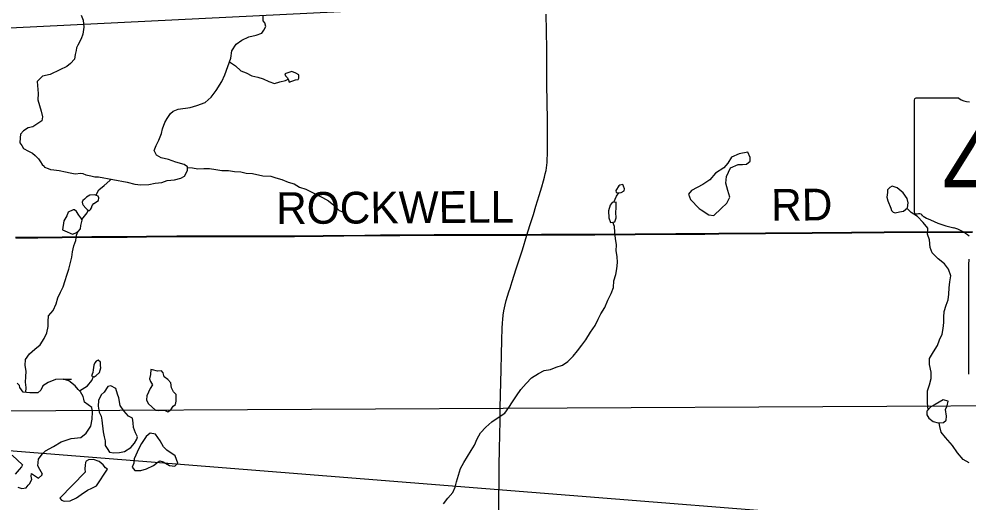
# Model space of a CAD drawing. Extents: x 0 to 34, y 0 to 22.
# Drawn here: x 6.128 to 7.83, y 16.749 to 17.616 of the extents above; entities that cross this region are included whole.
import ezdxf

# ---------------------------------------------------------------- set-up
doc = ezdxf.new("R2010")
doc.units = 0
for name, color, linetype in [('GM_X_Corporation', 7, 'Continuous'), ('GM_X_County_Road', 7, 'Continuous'), ('GM_X_County_Road_Text', 7, 'Continuous'), ('GM_X_Minor_Lake', 7, 'Continuous'), ('GM_X_Minor_River', 7, 'Continuous'), ('GM_X_State_Location', 7, 'Continuous'), ('GM_X_State_Route', 7, 'Continuous'), ('GM_X_State_Shield', 7, 'Continuous'), ('SH_Text', 7, 'Continuous')]:
    doc.layers.add(name, color=color, linetype=linetype)

msp = doc.modelspace()

# ---------------------------------------------------------------- linework, layer by layer
at = {"layer": 'GM_X_Corporation'}
for points in [[(7.8362, 17.2347), (7.6782, 17.2342), (7.6198, 17.2337), (7.549, 17.2329), (7.3818, 17.2314), (7.3564, 17.2312), (7.3048, 17.2311), (7.1593, 17.23), (7.1382, 17.2298), (7.1122, 17.2299), (7.0898, 17.2297), (7.0645, 17.2297), (7.0379, 17.2295), (7.0015, 17.2293), (6.9624, 17.2292), (6.9475, 17.2293), (6.9047, 17.2295), (6.8718, 17.2293), (6.8104, 17.229), (6.7756, 17.2286), (6.7476, 17.2284), (6.6731, 17.2276), (6.6215, 17.227), (6.5929, 17.2268), (6.5569, 17.2268), (6.5314, 17.2268), (6.4817, 17.2268), (6.4688, 17.2268), (6.4502, 17.2269), (6.4107, 17.2268), (6.3562, 17.2263), (6.3215, 17.2259), (6.3059, 17.2258), (6.2767, 17.2256), (6.2587, 17.2255), (6.2053, 17.2252), (6.1792, 17.2248), (6.1618, 17.2246), (6.122, 17.2243)], [(6.122, 17.2243), (6.1618, 17.2246), (6.1792, 17.2248), (6.2053, 17.2252), (6.2587, 17.2255), (6.2767, 17.2256), (6.3059, 17.2258), (6.3215, 17.2259), (6.3562, 17.2263), (6.4107, 17.2268), (6.4502, 17.2269), (6.4688, 17.2268), (6.4817, 17.2268), (6.5314, 17.2268), (6.5569, 17.2268), (6.5929, 17.2268), (6.6215, 17.227), (6.6731, 17.2276), (6.7476, 17.2284), (6.7756, 17.2286), (6.8104, 17.229), (6.8718, 17.2293), (6.9047, 17.2295), (6.9475, 17.2293), (6.9624, 17.2292), (7.0015, 17.2293), (7.0379, 17.2295), (7.0645, 17.2297), (7.0898, 17.2297), (7.1122, 17.2299), (7.1382, 17.2298), (7.1593, 17.23), (7.3048, 17.2311), (7.3564, 17.2312), (7.3818, 17.2314), (7.549, 17.2329), (7.6198, 17.2337), (7.6782, 17.2342), (7.8362, 17.2347)]]:
    msp.add_lwpolyline(points, dxfattribs=at)
at = {"layer": 'GM_X_County_Road'}
for points in [[(7.0381, 17.229), (7.0436, 17.2462), (7.0497, 17.2658), (7.0542, 17.2804), (7.0603, 17.2998), (7.0647, 17.315), (7.068, 17.3262), (7.0695, 17.3323), (7.071, 17.3384), (7.0723, 17.3447), (7.073, 17.3493), (7.0736, 17.3539), (7.0741, 17.3585), (7.0743, 17.3624), (7.0748, 17.3757), (7.0749, 17.3828), (7.0749, 17.3916), (7.0749, 17.407), (7.0748, 17.4352), (7.074, 17.4985), (7.0738, 17.5368), (7.0736, 17.5608), (7.0731, 17.5947), (7.0727, 17.6245)], [(6.1222, 17.2238), (6.162, 17.2241), (6.1794, 17.2243), (6.2055, 17.2246), (6.2589, 17.225), (6.2769, 17.2251), (6.3061, 17.2253), (6.3217, 17.2254), (6.3564, 17.2257), (6.4109, 17.2262), (6.4504, 17.2263), (6.469, 17.2263), (6.4819, 17.2263), (6.5316, 17.2263), (6.5571, 17.2262), (6.5931, 17.2263), (6.6217, 17.2264), (6.6733, 17.2271), (6.7478, 17.2279), (6.7758, 17.2281), (6.8106, 17.2284), (6.872, 17.2287), (6.9049, 17.2289), (6.9477, 17.2288), (6.9626, 17.2287), (7.0017, 17.2288), (7.0381, 17.229)], [(6.9878, 16.7338), (6.988, 16.7499), (6.988, 16.7679), (6.9881, 16.7791), (6.9882, 16.7871), (6.9885, 16.8157), (6.9891, 16.8462), (6.99, 16.8965), (6.9904, 16.9196), (6.9919, 16.9882), (6.9924, 17.0142), (6.9932, 17.0415), (6.9939, 17.0615), (6.9945, 17.0719), (6.9949, 17.0777), (6.9957, 17.0854), (6.9967, 17.0931), (6.9977, 17.0987), (6.999, 17.1039), (7.0012, 17.1116), (7.0057, 17.1271), (7.0078, 17.1336), (7.0117, 17.146), (7.019, 17.1684), (7.0301, 17.2027), (7.0381, 17.229)], [(7.0381, 17.229), (7.0647, 17.2291), (7.09, 17.2291), (7.1124, 17.2293), (7.1384, 17.2293), (7.1595, 17.2294), (7.305, 17.2305), (7.3566, 17.2307), (7.382, 17.2308), (7.5492, 17.2324), (7.62, 17.2331), (7.6784, 17.2336), (7.8364, 17.2342)]]:
    msp.add_lwpolyline(points, dxfattribs=at)
at = {"layer": 'GM_X_Minor_Lake'}
for p, q in [((6.6122, 17.5028), (6.6235, 17.5067)), ((6.2706, 17.333), (6.3218, 17.3235)), ((7.2029, 17.317), (7.1977, 17.3086)), ((6.243, 17.2827), (6.2477, 17.2768)), ((7.331, 17.2925), (7.347, 17.2767)), ((7.347, 17.2767), (7.3318, 17.2922)), ((7.6849, 17.29), (7.6899, 17.2768)), ((7.184, 17.2721), (7.1847, 17.2596)), ((6.2104, 17.2362), (6.2241, 17.2306)), ((6.2619, 16.9958), (6.2608, 16.9874)), ((6.3633, 16.9541), (6.3569, 16.9408)), ((7.7697, 16.9257), (7.7621, 16.9211)), ((6.2763, 16.8977), (6.2787, 16.8765)), ((6.1753, 16.8427), (6.1896, 16.8504)), ((6.3425, 16.8466), (6.3344, 16.8284)), ((6.267, 16.7797), (6.2868, 16.8098))]:
    msp.add_line(p, q, dxfattribs=at)
for points in [[(6.2392, 17.6225), (6.2431, 17.6138), (6.2439, 17.6013), (6.2425, 17.5884), (6.2395, 17.58), (6.2336, 17.569), (6.2313, 17.564), (6.2302, 17.5595), (6.2288, 17.5523), (6.2277, 17.5439), (6.2202, 17.5363), (6.2138, 17.5309), (6.2014, 17.5244), (6.184, 17.5166), (6.17, 17.5135), (6.1606, 17.5036), (6.1623, 17.4823), (6.1617, 17.471), (6.1679, 17.4505), (6.1702, 17.4403), (6.1691, 17.4335), (6.153, 17.4227), (6.1446, 17.4208), (6.136, 17.4154), (6.1307, 17.4093), (6.13, 17.4032), (6.1293, 17.3941), (6.1332, 17.3892), (6.1362, 17.3839), (6.145, 17.3791), (6.1522, 17.3757), (6.1568, 17.3716), (6.1629, 17.3655), (6.1667, 17.3599), (6.1698, 17.355), (6.1732, 17.352), (6.174, 17.3505), (6.18, 17.3478), (6.1842, 17.3464), (6.1906, 17.3457), (6.2001, 17.3442), (6.2115, 17.342), (6.2195, 17.3402), (6.2289, 17.3387), (6.2388, 17.3396), (6.2425, 17.3392), (6.2475, 17.337), (6.257, 17.3352), (6.2638, 17.3333), (6.2706, 17.333)], [(6.3218, 17.3235), (6.3354, 17.3202), (6.3464, 17.3188), (6.3604, 17.3193), (6.3717, 17.322), (6.3842, 17.3229), (6.3937, 17.3267), (6.4069, 17.3276), (6.4182, 17.3307), (6.4246, 17.3345), (6.4298, 17.3444), (6.4302, 17.3513), (6.4237, 17.3554), (6.4093, 17.3591), (6.3956, 17.3643), (6.3827, 17.3672), (6.3744, 17.3717), (6.3705, 17.38), (6.3739, 17.3895), (6.3787, 17.399), (6.3832, 17.4108), (6.385, 17.4192), (6.3894, 17.4306), (6.3935, 17.4378), (6.3992, 17.4466), (6.404, 17.4508), (6.4135, 17.4543), (6.435, 17.4571), (6.4467, 17.461), (6.4614, 17.4664), (6.4724, 17.4756), (6.4813, 17.4878), (6.4914, 17.5038), (6.4966, 17.5156), (6.5022, 17.5305), (6.5074, 17.5453), (6.5092, 17.5589), (6.5174, 17.5708), (6.5272, 17.5777), (6.5396, 17.5835), (6.5529, 17.587), (6.5631, 17.5905), (6.5668, 17.5958), (6.5701, 17.6023), (6.5682, 17.6087), (6.5655, 17.6125), (6.5658, 17.6212)], [(6.6235, 17.5067), (6.628, 17.5075), (6.6295, 17.5098), (6.6295, 17.5155), (6.6242, 17.5185), (6.6166, 17.5215), (6.6041, 17.5176), (6.6053, 17.5142), (6.6087, 17.5108), (6.611, 17.5066), (6.6122, 17.5028)], [(7.4337, 17.3771), (7.4182, 17.3744), (7.4046, 17.3686), (7.3983, 17.3575), (7.3911, 17.3491), (7.3761, 17.3399), (7.3656, 17.3277), (7.3535, 17.3196), (7.3328, 17.3089), (7.3275, 17.302), (7.331, 17.2925)], [(7.347, 17.2767), (7.3505, 17.2741), (7.3638, 17.2651), (7.3729, 17.2637), (7.3864, 17.2763), (7.3962, 17.2862), (7.4014, 17.2965), (7.3979, 17.3086), (7.3948, 17.3218), (7.3958, 17.334), (7.3991, 17.3416), (7.4029, 17.3492), (7.4165, 17.355), (7.4244, 17.3551), (7.4316, 17.3559), (7.438, 17.3609), (7.4379, 17.3677), (7.4337, 17.3771), (7.4182, 17.3744), (7.4046, 17.3686), (7.3983, 17.3575), (7.3911, 17.3491), (7.3761, 17.3399), (7.3656, 17.3277), (7.3535, 17.3196), (7.3328, 17.3089), (7.3275, 17.302), (7.331, 17.2925)], [(7.347, 17.2767), (7.3505, 17.2741), (7.3638, 17.2651), (7.3729, 17.2637), (7.3864, 17.2763), (7.3962, 17.2862), (7.4014, 17.2965), (7.3979, 17.3086), (7.3948, 17.3218), (7.3958, 17.334), (7.3991, 17.3416), (7.4029, 17.3492), (7.4165, 17.355), (7.4244, 17.3551), (7.4316, 17.3559), (7.438, 17.3609), (7.4379, 17.3677), (7.4337, 17.3771)], [(7.1977, 17.3086), (7.1981, 17.3052), (7.2034, 17.3045), (7.2072, 17.3052), (7.2121, 17.3083), (7.2128, 17.3117), (7.2112, 17.3163), (7.2101, 17.3193), (7.2044, 17.3185), (7.2029, 17.317)], [(7.6899, 17.2768), (7.6915, 17.273), (7.6946, 17.27), (7.698, 17.2689), (7.7059, 17.2705), (7.7128, 17.2717), (7.7199, 17.2779), (7.7213, 17.2866), (7.7197, 17.2942), (7.7124, 17.3043), (7.7017, 17.3137), (7.6926, 17.3163), (7.6884, 17.3139), (7.6843, 17.3097), (7.684, 17.3048), (7.6829, 17.2968), (7.6849, 17.29)], [(6.2477, 17.2768), (6.2499, 17.2748), (6.2537, 17.2722), (6.2563, 17.2749), (6.2578, 17.2779), (6.2593, 17.2821), (6.2619, 17.2855), (6.2702, 17.2909), (6.2713, 17.2954), (6.2697, 17.2985), (6.2637, 17.3007), (6.255, 17.3006), (6.2489, 17.2968), (6.2452, 17.293), (6.2422, 17.2907), (6.2414, 17.2876), (6.2418, 17.2846), (6.243, 17.2827)], [(7.1847, 17.2596), (7.1879, 17.2512), (7.1958, 17.2528), (7.1981, 17.26), (7.1976, 17.2691), (7.1979, 17.2779), (7.1978, 17.2877), (7.191, 17.2873), (7.1873, 17.2823), (7.184, 17.2721)], [(6.2241, 17.2306), (6.2286, 17.2322), (6.2343, 17.2352), (6.238, 17.2402), (6.2387, 17.2463), (6.2398, 17.2508), (6.2409, 17.2554), (6.2386, 17.2596), (6.2352, 17.2648), (6.2313, 17.2713), (6.2272, 17.2739), (6.2249, 17.2739), (6.2162, 17.2696), (6.2136, 17.2632), (6.2084, 17.2544), (6.2059, 17.2381), (6.2104, 17.2362)], [(6.2608, 16.9874), (6.2605, 16.9829), (6.2582, 16.9768), (6.2624, 16.9749), (6.2662, 16.9772), (6.2722, 16.9826), (6.2748, 16.9913), (6.274, 16.9955), (6.274, 17.0012), (6.2698, 17.0049), (6.2664, 17.003), (6.2641, 17.0004), (6.2619, 16.9958)], [(6.3569, 16.9408), (6.3566, 16.9339), (6.3597, 16.9271), (6.3669, 16.9208), (6.3723, 16.9155), (6.3787, 16.9148), (6.3889, 16.9156), (6.3946, 16.9126), (6.3999, 16.9161), (6.404, 16.9226), (6.4085, 16.9256), (6.4096, 16.9317), (6.4099, 16.9435), (6.4046, 16.9483), (6.4015, 16.9551), (6.3999, 16.9642), (6.3949, 16.9706), (6.3881, 16.9751), (6.3865, 16.9823), (6.3831, 16.9861), (6.3763, 16.9853), (6.3675, 16.9879), (6.3641, 16.9882), (6.3638, 16.9791), (6.362, 16.9715), (6.3635, 16.9666), (6.367, 16.9609), (6.3633, 16.9541)], [(6.1896, 16.8504), (6.2035, 16.8588), (6.2213, 16.8647), (6.2387, 16.8667), (6.2485, 16.874), (6.2567, 16.8865), (6.2592, 16.8991), (6.2595, 16.9123), (6.2583, 16.9203), (6.2518, 16.9248), (6.2454, 16.9297), (6.2442, 16.935), (6.243, 16.9399), (6.2384, 16.9482), (6.2338, 16.9523), (6.2285, 16.9587), (6.2174, 16.9681), (6.2072, 16.9707), (6.1932, 16.9706), (6.18, 16.9652), (6.1706, 16.9587), (6.1672, 16.9515), (6.162, 16.9465), (6.1472, 16.9464), (6.1355, 16.9474), (6.1297, 16.9561), (6.1289, 16.9595), (6.1248, 16.9636)], [(6.2787, 16.8765), (6.2807, 16.8678), (6.2822, 16.8606), (6.2827, 16.8522), (6.2861, 16.8469), (6.2904, 16.8405), (6.2979, 16.8391), (6.3078, 16.8395), (6.3172, 16.8415), (6.3285, 16.8484), (6.3349, 16.8564), (6.3394, 16.8633), (6.3401, 16.8675), (6.3366, 16.875), (6.3332, 16.8841), (6.3327, 16.8928), (6.3311, 16.9011), (6.3243, 16.9049), (6.3159, 16.9143), (6.3094, 16.9237), (6.3066, 16.9374), (6.3043, 16.9442), (6.3016, 16.9544), (6.2928, 16.9592), (6.2872, 16.9577), (6.2808, 16.9478), (6.2755, 16.9428), (6.2703, 16.9325), (6.27, 16.9227), (6.2716, 16.9117), (6.2751, 16.9045), (6.2763, 16.8977)], [(7.7621, 16.9211), (7.7547, 16.9138), (7.7547, 16.9069), (7.7582, 16.9013), (7.7662, 16.8953), (7.775, 16.8927), (7.7844, 16.8932), (7.7893, 16.8978), (7.79, 16.9047), (7.7883, 16.9164), (7.7913, 16.9233), (7.7931, 16.9313), (7.784, 16.9342), (7.7768, 16.93), (7.7697, 16.9257)], [(6.3344, 16.8284), (6.334, 16.8204), (6.3307, 16.8135), (6.3357, 16.8075), (6.3466, 16.8076), (6.3564, 16.8103), (6.3693, 16.8165), (6.3775, 16.823), (6.3806, 16.8245), (6.3866, 16.8231), (6.3977, 16.8163), (6.4075, 16.8153), (6.4124, 16.8206), (6.4077, 16.8335), (6.3929, 16.8436), (6.3872, 16.85), (6.381, 16.8606), (6.3726, 16.8723), (6.3628, 16.8741), (6.3556, 16.868), (6.3474, 16.8558), (6.3425, 16.8466)], [(6.1258, 16.7775), (6.133, 16.7752), (6.141, 16.7764), (6.1444, 16.781), (6.147, 16.7837), (6.1511, 16.7913), (6.1499, 16.797), (6.1502, 16.8019), (6.1632, 16.7937), (6.1688, 16.799), (6.1703, 16.8009), (6.1653, 16.8089), (6.1619, 16.816), (6.1629, 16.8278), (6.1693, 16.8366), (6.1753, 16.8427)], [(6.1159, 16.8347), (6.1342, 16.8177), (6.1324, 16.8139), (6.1282, 16.8093), (6.1211, 16.8006)], [(6.2868, 16.8098), (6.283, 16.8124), (6.2788, 16.8177), (6.2716, 16.8237), (6.2613, 16.827), (6.2526, 16.8262), (6.2481, 16.8239), (6.2474, 16.822), (6.2463, 16.8167), (6.2459, 16.8102), (6.2464, 16.8042), (6.2009, 16.7576), (6.204, 16.7542), (6.2089, 16.7523), (6.2199, 16.7528), (6.2308, 16.7582), (6.2395, 16.7647), (6.2508, 16.772), (6.2587, 16.7758), (6.267, 16.7797)]]:
    msp.add_lwpolyline(points, dxfattribs=at)
at = {"layer": 'GM_X_Minor_River'}
for points in [[(6.5053, 17.5392), (6.5158, 17.5321), (6.5253, 17.523), (6.5348, 17.5193), (6.5455, 17.5137), (6.5557, 17.5115), (6.5656, 17.5086), (6.5758, 17.5041), (6.5857, 17.5004), (6.5955, 17.5031), (6.6057, 17.5058), (6.6103, 17.5079)], [(6.4301, 17.3497), (6.4389, 17.3494), (6.4484, 17.3476), (6.4593, 17.3481), (6.4696, 17.3478), (6.4806, 17.346), (6.4912, 17.3445), (6.5036, 17.3446), (6.5139, 17.3424), (6.5256, 17.3418), (6.5351, 17.3399), (6.5461, 17.3389), (6.5647, 17.3352), (6.579, 17.3342), (6.5885, 17.3316), (6.5992, 17.3283), (6.6102, 17.3238), (6.6212, 17.3205), (6.6307, 17.3149), (6.6417, 17.3108), (6.6622, 17.3011), (6.6721, 17.2962), (6.6823, 17.2902), (6.6919, 17.2827), (6.7018, 17.2729), (6.7082, 17.2707)], [(6.2658, 17.2999), (6.2712, 17.3099), (6.2809, 17.3179), (6.2907, 17.3267), (6.2933, 17.3288)], [(7.194, 17.2875), (7.1989, 17.2988), (7.2027, 17.3046)], [(6.2403, 17.2565), (6.2499, 17.2687), (6.2522, 17.2732)], [(7.7572, 16.9162), (7.7556, 16.9286), (7.7558, 16.9502), (7.7594, 16.9609), (7.7623, 16.9719), (7.7626, 16.9833), (7.7594, 16.997), (7.7597, 17.008), (7.7667, 17.0198), (7.7738, 17.0309), (7.7775, 17.0416), (7.7819, 17.0515), (7.7837, 17.0618), (7.7854, 17.0724), (7.785, 17.0819), (7.786, 17.0922), (7.7896, 17.1033), (7.7929, 17.1128), (7.794, 17.123), (7.7946, 17.1344), (7.796, 17.1451), (7.7978, 17.1561), (7.7935, 17.1678), (7.7865, 17.1776), (7.7751, 17.1862), (7.764, 17.1971), (7.7608, 17.2069), (7.7592, 17.2202), (7.756, 17.2304), (7.7563, 17.2414), (7.7478, 17.2512), (7.7379, 17.2621), (7.7264, 17.2692), (7.7187, 17.2768)], [(6.9753, 16.8943), (6.9863, 16.9023), (6.9987, 16.91), (7.0058, 16.9203), (7.0125, 16.9306), (7.0196, 16.9409), (7.0271, 16.9527), (7.0365, 16.9634), (7.0466, 16.9733), (7.0587, 16.981), (7.0692, 16.9864), (7.0806, 16.988), (7.0904, 16.9923), (7.1017, 16.9958), (7.1115, 17.0023), (7.1209, 17.0122), (7.1288, 17.0217), (7.1363, 17.0317), (7.1438, 17.0412), (7.1523, 17.0549), (7.1602, 17.0671), (7.1658, 17.0781), (7.1706, 17.0877), (7.1777, 17.0995), (7.1829, 17.1124), (7.1889, 17.1242), (7.1934, 17.1352), (7.194, 17.147), (7.1973, 17.1584), (7.1995, 17.1683), (7.2006, 17.1797), (7.2001, 17.1907), (7.1978, 17.2009), (7.1984, 17.2115), (7.1968, 17.2229), (7.1956, 17.2339), (7.1948, 17.2445), (7.1922, 17.2521)], [(6.1405, 16.947), (6.1411, 16.9558), (6.1395, 16.9657), (6.1402, 16.9751), (6.1409, 16.9854), (6.1393, 16.9956), (6.1399, 17.0059), (6.1467, 17.0161), (6.1564, 17.0246), (6.1662, 17.0326), (6.1733, 17.0437), (6.1778, 17.0539), (6.18, 17.0649), (6.1803, 17.0744), (6.1806, 17.0843), (6.1892, 17.0938), (6.1944, 17.1056), (6.1977, 17.1163), (6.2022, 17.1265), (6.207, 17.1364), (6.2107, 17.1475), (6.2137, 17.157), (6.2174, 17.1676), (6.2225, 17.1896), (6.224, 17.1991), (6.2265, 17.2094), (6.2299, 17.2193), (6.2313, 17.2288), (6.2336, 17.2349)], [(6.2366, 16.9498), (6.2508, 16.9589), (6.2587, 16.9685), (6.2613, 16.9754)], [(6.2072, 16.9707), (6.2223, 16.9708)], [(6.8887, 16.748), (6.8966, 16.7576), (6.9056, 16.7679), (6.9093, 16.7774), (6.9122, 16.7873), (6.9155, 16.799), (6.9189, 16.8112), (6.9252, 16.8215), (6.9316, 16.8322), (6.9383, 16.8432), (6.9443, 16.8527), (6.9491, 16.8638), (6.9551, 16.8748), (6.9644, 16.8847), (6.9753, 16.8943)], [(7.8307, 16.8209), (7.82, 16.8272), (7.8097, 16.8392), (7.8008, 16.8524), (7.7881, 16.8663), (7.7805, 16.8761), (7.7777, 16.8859), (7.7769, 16.8928)]]:
    msp.add_lwpolyline(points, dxfattribs=at)
at = {"layer": 'GM_X_State_Route'}
msp.add_lwpolyline([(7.8302, 16.9796), (7.8301, 17.0048), (7.83, 17.0352), (7.8298, 17.1633), (7.8298, 17.1684), (7.8299, 17.1711), (7.83, 17.1753), (7.8305, 17.1855)], dxfattribs=at)
at = {"layer": 'GM_X_State_Shield'}
for p, q in [((7.7321, 17.4703), (7.7321, 17.2702)), ((7.8119, 17.4738), (7.7347, 17.4738))]:
    msp.add_line(p, q, dxfattribs=at)
for centre, radius, start, end in [((7.7351, 17.4708), 0.00305, 98.1301, 188.1301), ((7.8303, 17.497), 0.0296, 231.6195, 271.1119), ((7.7351, 17.2698), 0.00308, 171.9584, 258.3066), ((7.7356, 17.2903), 0.0235, 267.339, 280.6039), ((7.7404, 17.2587), 0.00848, 29.7484, 93.2717), ((7.8475, 17.4385), 0.2019, 240.4129, 257.1985), ((7.7873, 17.1803), 0.0632, 47.1842, 75.836)]:
    msp.add_arc(centre, radius, start, end, dxfattribs=at)
at = {"layer": 'SH_Text'}
for points in [[(9.4006, 18.113), (4.9378, 17.5422), (9.4006, 17.763)], [(9.4006, 16.931), (5.2772, 16.9092), (9.4006, 16.581)]]:
    msp.add_lwpolyline(points, close=True, dxfattribs=at)

# ---------------------------------------------------------------- texts
at = {"layer": 'GM_X_County_Road_Text'}
for s, rotation, p in [('RD', 0.4827, (7.4759, 17.2544)), ('ROCKWELL', 0.3709, (6.5889, 17.2486))]:
    msp.add_text(s, height=0.05682, rotation=rotation, dxfattribs=at).set_placement(p)
at = {"layer": 'GM_X_State_Location'}
msp.add_text('44', height=0.000189, rotation=0, dxfattribs=at).set_placement((7.8133, 17.3432))
at = {"layer": 'GM_X_State_Shield'}
msp.add_text('44', height=0.13184, dxfattribs=at).set_placement((7.7827, 17.2843))

doc.saveas('drawing.dxf')
